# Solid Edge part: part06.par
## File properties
Accuracy: 0.99
Author: Robert a Rhodes jr
Template: normal.par
Last saved by: Ashutosh-CADCIM
Revision: 11
Application: Solid Edge
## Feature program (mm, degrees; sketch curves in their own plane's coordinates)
sketch for "unnamed Protrusion 1" plane through (0, 0, 0) normal (0, -1, 0) x-axis (1, 0, 0)
  arc centre (60, 0) radius 30 from (60, 30) to (60, -30) cw
  line (104, -30) -> (60, -30)
  line (104, 18) -> (104, -30)
  line (164, 18) -> (104, 18)
  line (164, -4) -> (164, 18)
  line (182, -4) -> (164, -4)
  line (182, -4) -> (182, 36)
  line (142, 36) -> (182, 36)
  line (142, 30) -> (142, 36)
  line (60, 30) -> (142, 30)
extrude "unnamed Protrusion 1" add finite 54 symmetric
sketch for "ExtrudedProtrusion_6" #1 plane through (0, 0, 0) normal (0, -1, 0) x-axis (1, 0, 0)
  arc centre (60, 0) radius 30 from (60, 30) to (60, -30) ccw
  arc centre (60, 0) radius 30 from (60, 30) to (60, -30) cw
sketch for "ExtrudedProtrusion_6" #2 plane through (0, 0, 0) normal (0, -1, 0) x-axis (1, 0, 0)
  circle centre (60, 0) radius 18
extrude "ExtrudedProtrusion_6" add finite 66 symmetric
sketch for "ExtrudedProtrusion_7" plane through (0, 0, 0) normal (0, -1, 0) x-axis (1, 0, 0)
  line (104, -30) -> (164, -4)
  line (164, -4) -> (164, 18)
  line (164, 18) -> (104, 18)
  line (104, 18) -> (104, -30)
extrude "ExtrudedProtrusion_7" add finite 18 symmetric
sketch for "ExtrudedProtrusion_8" plane through (0, 0, 0) normal (0, -1, 0) x-axis (1, 0, 0)
  line (200, 76) -> (200, -4)
  line (200, -4) -> (182, -4)
  line (182, -4) -> (182, 36)
  line (182, 76) -> (182, 36)
  line (182, 76) -> (200, 76)
extrude "ExtrudedProtrusion_8" add finite 92 symmetric
sketch for "ExtrudedProtrusion_9" plane through (0, 0, 0) normal (0, -1, 0) x-axis (1, 0, 0)
  line (142, 36) -> (182, 76)
  line (182, 76) -> (182, 36)
  line (142, 36) -> (182, 36)
extrude "ExtrudedProtrusion_9" add finite 12 symmetric
sketch for "unnamed Hole 1" plane through (200, 0, 36) normal (1, 0, 0) x-axis (0, 1, 0)
hole "unnamed Hole 1" through
sketch for "Hole_1" plane through (200, 0, 36) normal (1, 0, 0) x-axis (0, 1, 0)
hole "Hole_1" diameter 16 through
pattern "unnamed Pattern 1" of "unnamed Hole 1", "Hole_1"
fillet "unnamed Round 1"
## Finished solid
Body 1: solid body, 34 faces, 81 edges, 46 vertices.
  Faces by surface: plane 28, cylinder 6
  Edges by curve: line 67, circle 14
Bounding box of the edges (mm): 170.000 x 92.000 x 106.000, from (30, -46, -30) to (200, 46, 76).
Cylindrical faces by radius (mm): R8 x2, R16 x2, R18 x1, R30 x1
Planar faces by outward normal: +x 3, +y 5, +z 4, -x 5, -y 5, -z 4, oblique 2
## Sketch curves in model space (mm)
circle centre (60, 0, 0) radius 18
line (182, 0, -4) -> (164, 0, -4)
line (104, 0, -30) -> (60, 0, -30)
arc centre (60, 0, 0) radius 30 from (60, 0, 30) through (30.0132, 0, -0.889) to (60, 0, -30)
arc centre (60, 0, 0) radius 30 from (60, 0, 30) through (89.9868, 0, -0.889) to (60, 0, -30)
line (142, 0, 36) -> (182, 0, 76)
line (142, 0, 36) -> (182, 0, 36)
line (104, 0, -30) -> (164, 0, -4)
line (182, 0, 76) -> (182, 0, 36)
line (182, 0, -4) -> (182, 0, 36)
line (142, 0, 30) -> (142, 0, 36)
line (60, 0, 30) -> (142, 0, 30)
line (104, 0, 18) -> (104, 0, -30)
line (164, 0, 18) -> (104, 0, 18)
line (164, 0, -4) -> (164, 0, 18)
line (200, 0, -4) -> (182, 0, -4)
line (200, 0, 76) -> (200, 0, -4)
line (182, 0, 76) -> (200, 0, 76)
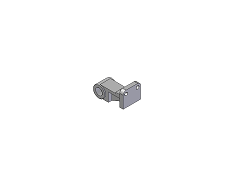
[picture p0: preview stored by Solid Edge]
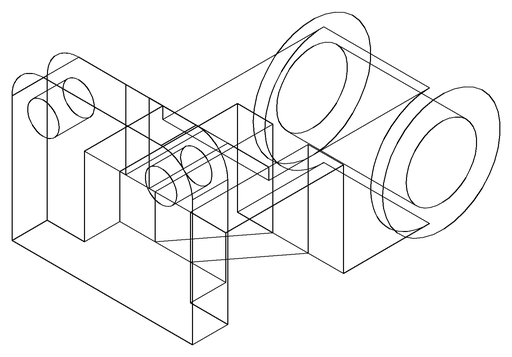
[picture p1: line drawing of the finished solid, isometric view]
